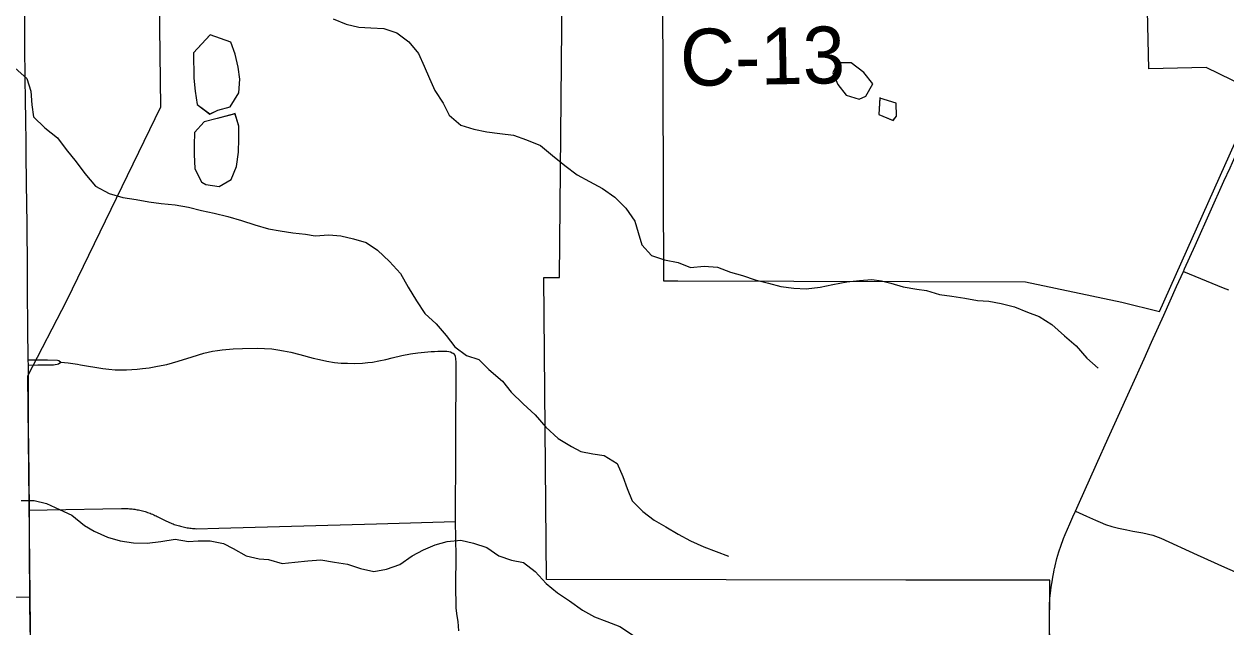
# Model space of a CAD drawing. Extents: x 0 to 34, y 0 to 22.
# Drawn here: x 4.726 to 5.326, y 20.115 to 20.416 of the extents above; entities that cross this region are included whole.
import ezdxf

# ---------------------------------------------------------------- set-up
doc = ezdxf.new("R2010")
doc.units = 0
for name, color, linetype in [('GM_X_City_Street', 7, 'Continuous'), ('GM_X_Corporation', 7, 'Continuous'), ('GM_X_County_Road', 7, 'Continuous'), ('GM_X_County_Road_Text', 7, 'Continuous'), ('GM_X_Minor_Lake', 7, 'Continuous'), ('GM_X_Minor_River', 7, 'Continuous'), ('GM_X_Rail_Line', 7, 'Continuous'), ('GM_X_Township_Road', 7, 'Continuous'), ('GM_X_US_Route', 7, 'Continuous')]:
    doc.layers.add(name, color=color, linetype=linetype)

msp = doc.modelspace()

# ---------------------------------------------------------------- linework, layer by layer
at = {"layer": 'GM_X_City_Street'}
for points in [[(5.30516, 20.29202), (5.32495, 20.28393), (5.32765, 20.28292)], [(5.25124, 20.17249), (5.25684, 20.17004), (5.25982, 20.16869), (5.26126, 20.16801), (5.26362, 20.16696), (5.26631, 20.16591), (5.26949, 20.16483), (5.27269, 20.16399), (5.27693, 20.16316), (5.27999, 20.16259), (5.28492, 20.16176), (5.2899, 20.16054), (5.29396, 20.15896), (5.31209, 20.15071), (5.32572, 20.1446), (5.33519, 20.14032)]]:
    msp.add_lwpolyline(points, dxfattribs=at)
at = {"layer": 'GM_X_Corporation'}
for points in [[(5.04517, 20.4325), (5.04562, 20.2874), (5.05281, 20.28738), (5.22639, 20.28699), (5.27446, 20.27677), (5.29321, 20.27218), (5.34214, 20.38148), (5.31652, 20.39385), (5.28791, 20.39324), (5.28697, 20.43682)], [(5.23784, 20.01902), (5.23848, 20.1381), (5.16655, 20.13812), (4.98712, 20.13835), (4.98582, 20.28913), (4.99362, 20.28913), (4.99492, 20.4316)]]:
    msp.add_lwpolyline(points, dxfattribs=at)
at = {"layer": 'GM_X_County_Road'}
msp.add_lwpolyline([(4.72941, 20.11209), (4.72914, 20.12962), (4.72904, 20.15257), (4.72898, 20.15927), (4.72909, 20.17305), (4.72866, 20.20495), (4.7286, 20.21289), (4.72855, 20.23112), (4.7285, 20.24535), (4.72845, 20.24795), (4.72818, 20.2642), (4.72807, 20.28238), (4.72802, 20.29064), (4.72796, 20.30034), (4.72791, 20.30887), (4.7278, 20.31578), (4.72753, 20.33605), (4.72743, 20.35079), (4.72735, 20.35819), (4.72727, 20.36613), (4.72705, 20.37926), (4.72694, 20.38688), (4.72678, 20.40581), (4.72677, 20.42069)], dxfattribs=at)
at = {"layer": 'GM_X_Minor_Lake'}
for points in [[(4.81923, 20.41014), (4.81091, 20.40111), (4.81114, 20.38857), (4.81183, 20.38212), (4.81272, 20.37549), (4.81913, 20.37063)], [(4.81907, 20.40998), (4.81091, 20.40111), (4.81114, 20.38857), (4.81183, 20.38212), (4.81272, 20.37549), (4.81906, 20.37068)], [(4.81913, 20.37063), (4.82302, 20.37264), (4.82925, 20.37428), (4.83348, 20.3812), (4.83411, 20.38805), (4.83324, 20.39411), (4.83179, 20.40055), (4.82959, 20.40659), (4.81923, 20.41014)], [(4.81922, 20.37068), (4.82302, 20.37264), (4.82925, 20.37428), (4.83348, 20.3812), (4.83411, 20.38805), (4.83324, 20.39411), (4.83179, 20.40055), (4.82959, 20.40659), (4.81923, 20.41014)], [(5.13244, 20.39628), (5.13005, 20.39129), (5.13263, 20.38545), (5.13671, 20.38002), (5.14325, 20.37803)], [(5.13228, 20.39595), (5.13005, 20.39129), (5.13263, 20.38545), (5.13671, 20.38002), (5.1432, 20.37805)], [(5.1432, 20.37801), (5.14659, 20.37963), (5.15008, 20.38578), (5.14561, 20.39139), (5.13926, 20.39621), (5.13242, 20.39628)], [(5.14325, 20.37803), (5.14659, 20.37963), (5.15008, 20.38578), (5.14561, 20.39139), (5.13926, 20.39621), (5.13244, 20.39628)], [(5.15363, 20.37882), (5.15314, 20.37034), (5.15999, 20.36757)], [(5.15361, 20.3785), (5.15314, 20.37034), (5.16024, 20.36747)], [(5.16024, 20.36747), (5.16195, 20.36966), (5.16183, 20.37611), (5.15361, 20.3785)], [(5.16031, 20.36757), (5.16195, 20.36966), (5.16183, 20.37611), (5.15363, 20.37849)], [(4.83169, 20.37074), (4.82271, 20.36845), (4.81629, 20.36681), (4.81146, 20.3614), (4.8112, 20.35513), (4.81129, 20.35038), (4.8116, 20.34354), (4.81492, 20.33671)], [(4.83145, 20.37067), (4.82271, 20.36845), (4.81629, 20.36681), (4.81146, 20.3614), (4.8112, 20.35513), (4.81129, 20.35038), (4.8116, 20.34354), (4.81497, 20.3366)], [(4.81492, 20.33671), (4.81707, 20.33547), (4.82373, 20.33446), (4.82973, 20.33799), (4.83246, 20.3445), (4.83347, 20.35155), (4.83353, 20.3582), (4.8336, 20.36466), (4.83169, 20.37074)], [(4.81515, 20.33658), (4.81707, 20.33547), (4.82373, 20.33446), (4.82973, 20.33799), (4.83246, 20.3445), (4.83347, 20.35155), (4.83353, 20.3582), (4.8336, 20.36466), (4.83158, 20.37109)]]:
    msp.add_lwpolyline(points, dxfattribs=at)
at = {"layer": 'GM_X_Minor_River'}
for points in [[(4.88061, 20.41818), (4.88711, 20.41545), (4.8934, 20.41405), (4.89948, 20.41359), (4.90593, 20.41333), (4.91242, 20.41117), (4.91839, 20.40672), (4.92324, 20.40092), (4.92602, 20.39452), (4.92879, 20.3883), (4.93137, 20.38245), (4.93566, 20.37607), (4.93862, 20.37005), (4.9444, 20.36502), (4.95089, 20.36305), (4.95737, 20.36184), (4.96383, 20.36102), (4.97068, 20.36019), (4.97717, 20.35784), (4.98425, 20.35494), (4.99022, 20.34992), (4.99639, 20.3449), (5.00255, 20.34026), (5.00868, 20.33696), (5.0152, 20.33347), (5.02135, 20.32921), (5.02677, 20.32361), (5.03125, 20.31724), (5.03287, 20.31157), (5.0347, 20.30533), (5.03954, 20.3001), (5.04603, 20.29794), (5.05289, 20.29655), (5.059, 20.294), (5.06582, 20.2947), (5.07247, 20.29425), (5.07897, 20.29171), (5.08507, 20.29012), (5.09137, 20.28795), (5.09805, 20.28618), (5.10415, 20.28458), (5.11062, 20.28375), (5.11688, 20.28349), (5.12389, 20.28419), (5.13013, 20.28564), (5.13712, 20.28691), (5.14337, 20.2876), (5.14962, 20.28809), (5.15438, 20.28742), (5.15915, 20.28618), (5.16525, 20.28439), (5.1721, 20.28319), (5.17686, 20.28252), (5.18335, 20.28055), (5.18962, 20.27972), (5.1961, 20.2787), (5.20238, 20.27768), (5.20808, 20.27721), (5.21417, 20.27618), (5.22084, 20.27441), (5.22734, 20.27187), (5.23307, 20.2697), (5.23941, 20.26563), (5.24578, 20.26005), (5.25156, 20.25503), (5.25699, 20.24886), (5.26259, 20.24383)], [(4.72187, 20.39355), (4.72766, 20.38834), (4.72968, 20.38211), (4.73018, 20.37528), (4.73105, 20.36921), (4.73666, 20.36381), (4.74301, 20.35879), (4.7473, 20.35298), (4.75234, 20.34681), (4.75663, 20.34099), (4.76206, 20.33464), (4.76877, 20.33096), (4.77564, 20.329), (4.7823, 20.32798), (4.78858, 20.32677), (4.79486, 20.32594), (4.8017, 20.3253), (4.80836, 20.3241), (4.81484, 20.32251), (4.82132, 20.32111), (4.82799, 20.31952), (4.83486, 20.31756), (4.84154, 20.31541), (4.84841, 20.31344), (4.85412, 20.31241), (4.86059, 20.31139), (4.86686, 20.31075), (4.87162, 20.30989), (4.87844, 20.31039), (4.88452, 20.30994), (4.89081, 20.30834), (4.89711, 20.30656), (4.90287, 20.30268), (4.90886, 20.29709), (4.91428, 20.29111), (4.91802, 20.28434), (4.92232, 20.27739), (4.92642, 20.27119), (4.93202, 20.26598), (4.93706, 20.26018), (4.94134, 20.25456), (4.94731, 20.25011), (4.95341, 20.24813), (4.95844, 20.2431), (4.96519, 20.23733), (4.96947, 20.2319), (4.97546, 20.22612), (4.98144, 20.22053), (4.98687, 20.21436), (4.99305, 20.20878), (4.99957, 20.20472), (5.00436, 20.20234), (5.01027, 20.20112), (5.01598, 20.20027), (5.0225, 20.19621), (5.02528, 20.18981), (5.02748, 20.18377), (5.02987, 20.17773), (5.03528, 20.17232), (5.04086, 20.16805), (5.04681, 20.16474), (5.05295, 20.16106), (5.05908, 20.15775), (5.06578, 20.15465), (5.07189, 20.15229), (5.07801, 20.15012)], [(4.72495, 20.17774), (4.7314, 20.17786), (4.7375, 20.17626), (4.74401, 20.17334), (4.75013, 20.17042), (4.75649, 20.16541), (4.76129, 20.16245), (4.76798, 20.15954), (4.77428, 20.15776), (4.78094, 20.15674), (4.78777, 20.15649), (4.79459, 20.15737), (4.80178, 20.15846), (4.80844, 20.15744), (4.81317, 20.15772), (4.81925, 20.15764), (4.82591, 20.15644), (4.8307, 20.15387), (4.83722, 20.15019), (4.8437, 20.14879), (4.84845, 20.14831), (4.85513, 20.14634), (4.86157, 20.14703), (4.86801, 20.14772), (4.87445, 20.14822), (4.8813, 20.14702), (4.88777, 20.146), (4.89426, 20.14384), (4.90093, 20.14245), (4.90736, 20.14352), (4.91396, 20.14592), (4.92014, 20.15022), (4.92578, 20.15317), (4.93161, 20.15575)], [(4.93161, 20.15575), (4.93765, 20.15739), (4.94447, 20.15808), (4.95076, 20.15649), (4.95744, 20.15433), (4.9634, 20.15026), (4.9697, 20.1481), (4.97561, 20.14688), (4.98157, 20.14243), (4.987, 20.13645), (4.99258, 20.13181), (4.99873, 20.12774), (5.00508, 20.12311), (5.01121, 20.1198), (5.01733, 20.11745), (5.02383, 20.11491), (5.03055, 20.11047)]]:
    msp.add_lwpolyline(points, dxfattribs=at)
at = {"layer": 'GM_X_Rail_Line'}
msp.add_lwpolyline([(4.76791, 17.00293), (4.79375, 17.14663), (4.79991, 17.2068), (4.80568, 17.24767), (4.80796, 17.29563), (4.80745, 17.36765), (4.80531, 17.38086), (4.79833, 17.40059), (4.77663, 17.43675), (4.76364, 17.46488), (4.7557, 17.50103), (4.75403, 17.51651), (4.75612, 17.80268), (4.75391, 18.09859), (4.74923, 18.38092), (4.74367, 18.7078), (4.73815, 19.14265), (4.73332, 19.55441), (4.7315, 19.92628), (4.72821, 20.24009), (4.74767, 20.27759), (4.79462, 20.37419), (4.79387, 20.42708)], dxfattribs=at)
at = {"layer": 'GM_X_Township_Road'}
for points in [[(4.74476, 20.24682), (4.74829, 20.24648), (4.75304, 20.2458), (4.75449, 20.24558), (4.76563, 20.24375), (4.76869, 20.2433), (4.7718, 20.24308), (4.77458, 20.24303), (4.77753, 20.24308), (4.78275, 20.24341), (4.78547, 20.24364), (4.78881, 20.24403), (4.79303, 20.2448), (4.79753, 20.24575), (4.80042, 20.24647), (4.8032, 20.2473), (4.8102, 20.24947), (4.81615, 20.25125), (4.81821, 20.25181), (4.82043, 20.25225), (4.82287, 20.25269), (4.82526, 20.25297), (4.83076, 20.25342), (4.83538, 20.25358), (4.84282, 20.25375), (4.84633, 20.2537), (4.85, 20.25342), (4.85305, 20.25303), (4.85589, 20.25253), (4.85955, 20.25177), (4.86405, 20.25064), (4.87067, 20.24886), (4.87383, 20.24812), (4.8775, 20.2473), (4.88134, 20.24669), (4.88467, 20.24636), (4.88773, 20.24629), (4.89117, 20.24625), (4.89529, 20.24642), (4.89801, 20.24665), (4.90029, 20.24692), (4.90346, 20.24747), (4.9069, 20.24819), (4.91018, 20.24903), (4.9149, 20.25014), (4.91935, 20.25103), (4.92296, 20.25153), (4.928, 20.25199), (4.92965, 20.25212), (4.93131, 20.25222), (4.93296, 20.25229), (4.93462, 20.25233), (4.93741, 20.25225), (4.93836, 20.25214), (4.93925, 20.25192), (4.94003, 20.25158), (4.94064, 20.25125), (4.94119, 20.25075)], [(4.72845, 20.24795), (4.73581, 20.248), (4.73807, 20.24805), (4.7431, 20.24787), (4.74375, 20.24764), (4.74476, 20.24682)], [(4.94342, 20.11276), (4.94325, 20.11515), (4.94299, 20.11737), (4.94258, 20.12021), (4.94203, 20.1241), (4.94197, 20.13593), (4.94208, 20.14966), (4.94193, 20.159), (4.9418, 20.16728), (4.94186, 20.20396), (4.9419, 20.21863), (4.94203, 20.2353), (4.94214, 20.24253), (4.94203, 20.24669), (4.94191, 20.24869), (4.94175, 20.24964), (4.94119, 20.25075)], [(4.7285, 20.24535), (4.73328, 20.24552), (4.74106, 20.24557), (4.74184, 20.24565), (4.74292, 20.24583), (4.7435, 20.24604), (4.74476, 20.24682)], [(4.72909, 20.17305), (4.73793, 20.17322), (4.77496, 20.17385), (4.77826, 20.17378), (4.77892, 20.17373), (4.77958, 20.17368), (4.78023, 20.1736), (4.78089, 20.17352), (4.78155, 20.17343), (4.7822, 20.17332), (4.78285, 20.17321), (4.7835, 20.17308), (4.78415, 20.17294), (4.78479, 20.17279), (4.78543, 20.17263), (4.78607, 20.17246), (4.78671, 20.17227), (4.78734, 20.17208), (4.78797, 20.17187), (4.78859, 20.17165), (4.78921, 20.17143), (4.78983, 20.17119), (4.79044, 20.17094), (4.79105, 20.17068), (4.79166, 20.17041), (4.79225, 20.17013), (4.79285, 20.16984), (4.79709, 20.16771), (4.79827, 20.16714), (4.79888, 20.16687), (4.79948, 20.16662), (4.8001, 20.16637), (4.80072, 20.16613), (4.80134, 20.1659), (4.80196, 20.16569), (4.80259, 20.16548), (4.80322, 20.16529), (4.80386, 20.16511), (4.8045, 20.16494), (4.80514, 20.16478), (4.80579, 20.16463), (4.80643, 20.16449), (4.80708, 20.16436), (4.80774, 20.16425), (4.80839, 20.16414), (4.80904, 20.16405), (4.8097, 20.16397), (4.81036, 20.1639), (4.81102, 20.16385), (4.81168, 20.1638), (4.81234, 20.16376), (4.82358, 20.16396), (4.90223, 20.16617), (4.9418, 20.16728)], [(4.71601, 20.12973), (4.72914, 20.12962)]]:
    msp.add_lwpolyline(points, dxfattribs=at)
at = {"layer": 'GM_X_US_Route'}
msp.add_line((5.29534, 20.27036), (5.30171, 20.28452), dxfattribs=at)
for points in [[(5.30171, 20.28452), (5.30516, 20.29202), (5.30574, 20.29346), (5.31102, 20.30511), (5.31167, 20.30655), (5.32542, 20.33715), (5.32849, 20.34373), (5.32972, 20.3465), (5.33582, 20.36027), (5.34356, 20.37749), (5.34699, 20.38512)], [(5.27183, 20.21814), (5.27906, 20.2342), (5.28552, 20.24855), (5.28925, 20.25683), (5.29534, 20.27036)], [(5.2408, 20.14399), (5.2409, 20.14442), (5.24108, 20.1452), (5.24201, 20.1488), (5.24296, 20.15222), (5.24409, 20.15546), (5.24509, 20.15829), (5.24529, 20.15882), (5.24608, 20.16092), (5.24726, 20.16356), (5.24839, 20.16618), (5.24994, 20.16965), (5.25124, 20.17249), (5.25265, 20.17554), (5.26185, 20.19595), (5.26765, 20.20885), (5.27183, 20.21814)], [(5.23912, 20.01761), (5.23917, 20.02584), (5.23906, 20.03793), (5.23879, 20.05479), (5.23845, 20.07256), (5.2384, 20.109), (5.23835, 20.11402), (5.23825, 20.12543), (5.23854, 20.12911), (5.23873, 20.13153), (5.23922, 20.13465), (5.23977, 20.13822), (5.23981, 20.13852), (5.2406, 20.14307), (5.2408, 20.14399)]]:
    msp.add_lwpolyline(points, dxfattribs=at)

# ---------------------------------------------------------------- texts
at = {"layer": 'GM_X_County_Road_Text'}
msp.add_text('C-13', height=0.028409, rotation=1.0299, dxfattribs=at).set_placement((5.05409, 20.3846))

doc.saveas('drawing.dxf')
